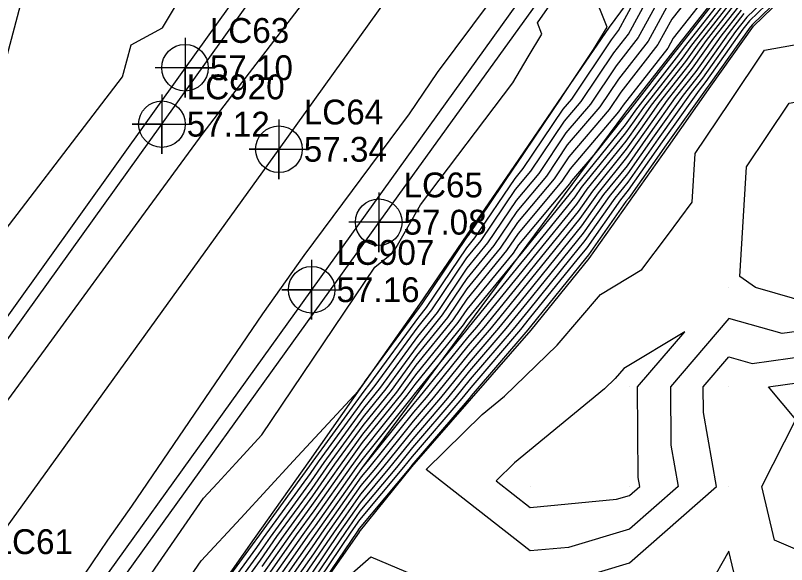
# Model space of a CAD drawing. Extents: x 2188792 to 2191981, y 386090 to 389710.
# Drawn here: x 2189698.4 to 2189776.1, y 387002.3 to 387057.5 of the extents above; entities that cross this region are included whole.
import ezdxf

# ---------------------------------------------------------------- set-up
doc = ezdxf.new("R2010")
doc.units = 0
for name, color, linetype in [('DTM Contours Major', 7, 'Continuous'), ('DTM Contours Minor', 7, 'Continuous'), ('Exist DTM QL2 LIDAR Elevation Point', 7, 'Continuous'), ('Exist Roads EOP', 7, 'Continuous'), ('Exist Roads EOP Cogo Elevation', 7, 'Continuous'), ('Exist Roads EOP Cogo Number', 7, 'Continuous'), ('Exist Roads EOP Cogo Point CELL', 7, 'Continuous'), ('Exist Roads EOT', 7, 'Continuous'), ('Exist Roads EOT Cogo Elevation', 7, 'Continuous'), ('Exist Roads EOT Cogo Number', 7, 'Continuous'), ('Exist Roads EOT Cogo Point CELL', 7, 'Continuous'), ('PH Exist DTM Breakline', 7, 'Continuous')]:
    doc.layers.add(name, color=color, linetype=linetype)

msp = doc.modelspace()

# ---------------------------------------------------------------- linework, layer by layer
at = {"layer": 'DTM Contours Major'}
for points in [[(2189690.321, 386970.473), (2189702.993, 386988.788), (2189704.322, 386990.511), (2189705.738, 386992.346), (2189707.249, 386994.304), (2189717.366, 387008.941), (2189718.756, 387010.444), (2189720.618, 387012.458), (2189723.242, 387015.296), (2189734.595, 387032.184), (2189736.495, 387033.703), (2189737.964, 387036.279), (2189739.21, 387038.462), (2189748.491, 387050.734), (2189750.059, 387053.337), (2189751.431, 387055.614), (2189750.977, 387056.76), (2189764.817, 387076.56)], [(2189770.37, 387059.498), (2189766.477, 387054.529), (2189765.536, 387053.205), (2189761.639, 387048.232), (2189760.7, 387046.911), (2189759.834, 387045.683), (2189755.394, 387040.191), (2189754.733, 387039.253), (2189749.901, 387033.319), (2189749.274, 387032.543), (2189744.104, 387026.197), (2189743.867, 387025.921), (2189741.118, 387022.531), (2189738.569, 387019.387), (2189738.376, 387019.123), (2189733.284, 387012.793), (2189732.715, 387012.012), (2189728.599, 387006.151), (2189728.008, 387005.341), (2189723.907, 386999.502)], [(2189764.365, 387059.07), (2189762.119, 387054.93), (2189759.122, 387051.105), (2189757.255, 387048.316), (2189753.984, 387044.476), (2189751.876, 387041.338), (2189748.903, 387037.778), (2189746.599, 387034.358), (2189743.864, 387031.031), (2189741.397, 387027.375), (2189738.858, 387024.244), (2189735.713, 387019.939), (2189733.438, 387017.112), (2189730.023, 387012.424), (2189728.266, 387009.921), (2189724.72, 387005.059), (2189723.055, 387002.687), (2189719.368, 386997.637)], [(2189771.771, 387057.69), (2189770.182, 387055.661), (2189767.252, 387051.539), (2189765.651, 387049.496), (2189762.729, 387045.388), (2189760.033, 387041.567), (2189758.204, 387039.304), (2189755.59, 387035.598), (2189753.605, 387033.16), (2189749.906, 387028.583), (2189747.795, 387025.992), (2189744.151, 387021.741), (2189741.932, 387019.006), (2189738.424, 387014.917), (2189736.076, 387012.007), (2189733.129, 387008.475), (2189731.016, 387005.466), (2189728.189, 387001.282)], [(2189780.243, 387002.408), (2189774.836, 387004.714), (2189773.564, 387010.122), (2189776.981, 387016.86), (2189774.225, 387020.123), (2189780.243, 387020.978), (2189780.976, 387020.123), (2189781.842, 387018.524), (2189784.658, 387010.122), (2189780.243, 387002.408)]]:
    msp.add_lwpolyline(points, dxfattribs=at)
at = {"layer": 'DTM Contours Minor'}
for points in [[(2189809.4, 387152.406), (2189801.396, 387139.864), (2189794.846, 387131.758), (2189788.146, 387120.877), (2189781.876, 387111.472), (2189771.155, 387095.136), (2189767.896, 387090.241), (2189758.451, 387075.833), (2189755.214, 387070.994), (2189740.876, 387051.783), (2189738.057, 387047.608), (2189727.447, 387033.342), (2189723.289, 387027.488), (2189710.113, 387008.133), (2189707.688, 387004.715), (2189696.068, 386987.603)], [(2189696.471, 387049.421), (2189699.118, 387059.215), (2189708.661, 387064.393), (2189716.242, 387077.088), (2189716.33, 387084.342), (2189716.986, 387089.265), (2189724.478, 387097.632), (2189725.68, 387102.327), (2189726.316, 387104.883), (2189727.566, 387106.251), (2189729.192, 387108.705), (2189725.665, 387114.356), (2189721.969, 387117.878), (2189720.487, 387119.888), (2189714.937, 387125.854), (2189714.651, 387126.766), (2189711.679, 387129.357), (2189708.744, 387132.995), (2189708.343, 387133.816), (2189703.681, 387138.317), (2189702.831, 387140.801), (2189699.533, 387144.461), (2189697.848, 387149.71)], [(2189696.907, 387017.785), (2189701.439, 387023.972), (2189711.162, 387037.242), (2189717.34, 387045.675), (2189728.32, 387060.015), (2189733.86, 387067.386), (2189739.131, 387074.278), (2189747.437, 387085.333), (2189756.453, 387096.182), (2189763.575, 387105.718), (2189769.232, 387112.608), (2189780.82, 387128.185), (2189787.157, 387139.391), (2189793.588, 387149.149)], [(2189693.956, 387031.466), (2189709.218, 387051.316), (2189710.092, 387054.548), (2189713.24, 387056.257), (2189723.102, 387072.77)], [(2189820.247, 387004.866), (2189810.804, 387009.564), (2189810.246, 387008.7), (2189810.022, 387009.897), (2189809.682, 387010.122), (2189803.138, 387013.015), (2189800.245, 387015.476), (2189796.388, 387016.266), (2189790.244, 387015.277), (2189787.619, 387020.123), (2189780.243, 387028.73), (2189778.618, 387028.499), (2189772.927, 387030.124), (2189771.347, 387031.229), (2189772.012, 387042.269), (2189774.139, 387045.431), (2189776.314, 387048.667), (2189788.413, 387050.787), (2189788.816, 387051.179), (2189789.608, 387051.909), (2189788.726, 387065.168)], [(2189717.798, 386997.228), (2189722.714, 387003.962), (2189723.405, 387004.946), (2189728.132, 387011.429), (2189728.947, 387012.589), (2189733.5, 387018.839), (2189734.647, 387020.265), (2189738.974, 387026.187), (2189740.343, 387027.876), (2189743.872, 387033.102), (2189745.319, 387034.863), (2189748.781, 387040.003), (2189750.324, 387041.85), (2189753.707, 387046.886), (2189755.368, 387048.836), (2189758.653, 387053.743), (2189760.14, 387055.641), (2189764.093, 387062.926)], [(2189780.243, 387026.146), (2189775.606, 387025.487), (2189770.242, 387027.018), (2189764.362, 387020.123), (2189764.402, 387014.282), (2189765.149, 387010.122), (2189760.241, 387005.813), (2189754.098, 387003.978), (2189750.24, 387003.616), (2189739.784, 387011.833), (2189745.409, 387017.359), (2189747.649, 387019.202), (2189752.969, 387024.33), (2189757.324, 387029.426), (2189761.491, 387031.946), (2189764.057, 387035.381), (2189766.554, 387038.726), (2189766.849, 387043.614), (2189770.309, 387048.76), (2189773.849, 387054.026), (2189777.609, 387054.685), (2189780.392, 387057.388), (2189785.853, 387062.425)], [(2189717.013, 386997.024), (2189722.543, 387004.599), (2189722.747, 387004.89), (2189728.066, 387012.183), (2189728.409, 387012.672), (2189733.531, 387019.703), (2189734.114, 387020.428), (2189739.031, 387027.158), (2189739.816, 387028.126), (2189743.875, 387034.138), (2189744.679, 387035.116), (2189748.72, 387041.116), (2189749.548, 387042.106), (2189753.568, 387048.091), (2189754.424, 387049.096), (2189758.419, 387055.063), (2189759.151, 387055.997), (2189762.508, 387062.186)], [(2189764.229, 387060.998), (2189761.129, 387055.285), (2189758.888, 387052.424), (2189756.312, 387048.576), (2189753.845, 387045.681), (2189751.1, 387041.594), (2189748.842, 387038.891), (2189745.959, 387034.611), (2189743.868, 387032.066), (2189740.87, 387027.626), (2189738.916, 387025.216), (2189735.18, 387020.102), (2189733.469, 387017.976), (2189729.485, 387012.507), (2189728.199, 387010.675), (2189724.062, 387005.003), (2189722.884, 387003.325), (2189718.583, 386997.433)], [(2189767.949, 387061.541), (2189764.501, 387057.141), (2189763.108, 387054.574), (2189759.357, 387049.786), (2189758.199, 387048.057), (2189754.123, 387043.271), (2189752.653, 387041.082), (2189748.964, 387036.666), (2189747.239, 387034.105), (2189743.861, 387029.995), (2189741.923, 387027.125), (2189738.8, 387023.273), (2189736.245, 387019.776), (2189733.408, 387016.248), (2189730.562, 387012.342), (2189728.332, 387009.167), (2189725.378, 387005.115), (2189723.225, 387002.05)], [(2189769.026, 387060.814), (2189764.637, 387055.213), (2189764.098, 387054.218), (2189759.591, 387048.467), (2189759.143, 387047.797), (2189754.261, 387042.066), (2189753.429, 387040.826), (2189749.025, 387035.553), (2189747.878, 387033.852), (2189743.857, 387028.959), (2189742.45, 387026.875), (2189738.743, 387022.301), (2189736.778, 387019.613), (2189733.377, 387015.384), (2189731.1, 387012.259), (2189728.399, 387008.413), (2189726.035, 387005.172), (2189723.396, 387001.413)], [(2189769.81, 387060.221), (2189764.996, 387054.076), (2189764.849, 387053.871), (2189760.035, 387047.726), (2189759.889, 387047.521), (2189759.754, 387047.33), (2189756.848, 387043.734), (2189754.4, 387040.861), (2189754.205, 387040.57), (2189749.085, 387034.441), (2189748.518, 387033.599), (2189743.854, 387027.923), (2189742.977, 387026.625), (2189738.685, 387021.33), (2189737.311, 387019.45), (2189733.346, 387014.521), (2189731.638, 387012.177), (2189728.465, 387007.659), (2189726.693, 387005.228), (2189723.566, 387000.776)], [(2189776.307, 387060.195), (2189772.612, 387056.605), (2189772.404, 387056.34), (2189768.281, 387050.54), (2189768.058, 387050.255), (2189763.947, 387044.473), (2189760.153, 387039.097), (2189759.89, 387038.771), (2189756.104, 387033.405), (2189755.828, 387033.065), (2189750.285, 387026.207), (2189750.009, 387025.869), (2189744.321, 387019.234), (2189744.103, 387018.964), (2189738.343, 387012.251), (2189738.193, 387012.065), (2189733.037, 387005.884), (2189732.78, 387005.517), (2189727.833, 386998.195)], [(2189775.671, 387060.211), (2189772.332, 387056.967), (2189771.663, 387056.114), (2189767.938, 387050.873), (2189767.256, 387050.002), (2189763.541, 387044.778), (2189760.113, 387039.92), (2189759.328, 387038.949), (2189755.933, 387034.136), (2189755.087, 387033.097), (2189750.159, 387026.999), (2189749.271, 387025.91), (2189744.265, 387020.07), (2189743.379, 387018.978), (2189738.37, 387013.14), (2189737.487, 387012.046), (2189733.068, 387006.747), (2189732.192, 387005.5), (2189727.951, 386999.224)], [(2189775.034, 387060.226), (2189772.051, 387057.328), (2189770.922, 387055.887), (2189767.595, 387051.206), (2189766.453, 387049.749), (2189763.135, 387045.083), (2189760.073, 387040.743), (2189758.766, 387039.126), (2189755.761, 387034.867), (2189754.346, 387033.128), (2189750.032, 387027.791), (2189748.533, 387025.951), (2189744.208, 387020.906), (2189742.656, 387018.992), (2189738.397, 387014.028), (2189736.782, 387012.026), (2189733.099, 387007.611), (2189731.604, 387005.483), (2189728.07, 387000.253)], [(2189694.937, 386972.126), (2189701.702, 386981.904), (2189705.036, 386986.223), (2189708.586, 386990.823), (2189712.374, 386995.732), (2189717.133, 387002.617), (2189721.107, 387006.915), (2189726.432, 387012.673), (2189732.935, 387019.706), (2189733.562, 387020.567), (2189733.582, 387020.591), (2189739.089, 387028.13), (2189739.289, 387028.377), (2189743.879, 387035.174), (2189744.039, 387035.369), (2189748.66, 387042.228), (2189748.771, 387042.362), (2189753.429, 387049.296), (2189753.48, 387049.355), (2189756.636, 387054.069), (2189757.992, 387056.32), (2189756.554, 387059.949)], [(2189770.09, 387059.859), (2189765.736, 387054.303), (2189765.193, 387053.538), (2189760.837, 387047.979), (2189760.295, 387047.216), (2189759.794, 387046.507), (2189754.833, 387040.369), (2189754.561, 387039.985), (2189749.16, 387033.351), (2189749.148, 387033.335), (2189748.983, 387033.133), (2189743.85, 387026.887), (2189743.504, 387026.374), (2189738.627, 387020.359), (2189737.844, 387019.286), (2189733.315, 387013.657), (2189732.177, 387012.094), (2189728.532, 387006.905), (2189727.35, 387005.284), (2189723.737, 387000.139)], [(2189770.65, 387059.136), (2189767.218, 387054.755), (2189765.879, 387052.872), (2189762.442, 387048.485), (2189761.106, 387046.606), (2189759.874, 387044.86), (2189755.956, 387040.014), (2189754.904, 387038.522), (2189750.642, 387033.287), (2189749.4, 387031.751), (2189744.842, 387026.156), (2189743.924, 387025.085), (2189739.038, 387019.061), (2189738.532, 387018.472), (2189733.253, 387011.929), (2189728.665, 387005.397), (2189724.078, 386998.864)], [(2189770.931, 387058.774), (2189767.959, 387054.982), (2189766.222, 387052.538), (2189763.244, 387048.738), (2189761.512, 387046.302), (2189759.914, 387044.037), (2189756.518, 387039.836), (2189755.076, 387037.791), (2189751.383, 387033.255), (2189749.527, 387030.959), (2189745.58, 387026.115), (2189743.981, 387024.249), (2189739.761, 387019.047), (2189738.505, 387017.583), (2189733.959, 387011.949), (2189733.222, 387011.066), (2189729.253, 387005.414), (2189728.546, 387004.368), (2189724.606, 386998.758)], [(2189771.211, 387058.413), (2189768.7, 387055.208), (2189766.565, 387052.205), (2189764.046, 387048.991), (2189761.918, 387045.997), (2189759.954, 387043.213), (2189757.08, 387039.659), (2189755.247, 387037.06), (2189752.124, 387033.224), (2189749.653, 387030.167), (2189746.318, 387026.074), (2189744.038, 387023.413), (2189740.485, 387019.033), (2189738.478, 387016.694), (2189734.664, 387011.968), (2189733.191, 387010.202), (2189729.841, 387005.431), (2189728.427, 387003.339), (2189725.135, 386998.652)], [(2189771.491, 387058.051), (2189769.441, 387055.435), (2189766.909, 387051.872), (2189764.849, 387049.244), (2189762.324, 387045.692), (2189759.993, 387042.39), (2189757.642, 387039.481), (2189755.419, 387036.329), (2189752.864, 387033.192), (2189749.78, 387029.375), (2189747.057, 387026.033), (2189744.094, 387022.577), (2189741.208, 387019.019), (2189738.451, 387015.806), (2189735.37, 387011.988), (2189733.16, 387009.338), (2189730.429, 387005.449), (2189728.308, 387002.31), (2189725.664, 386998.545)], [(2189761.06, 387020.123), (2189765.803, 387025.685), (2189759.662, 387021.972), (2189758.796, 387020.959), (2189757.739, 387019.94), (2189748.668, 387012.477), (2189746.837, 387010.679), (2189750.24, 387008.004), (2189758.941, 387008.821), (2189760.241, 387009.21), (2189761.28, 387010.122), (2189761.122, 387011.003), (2189761.06, 387020.123)], [(2189770.901, 387000.78), (2189770.242, 387003.583), (2189768.255, 387000.121), (2189762.025, 386998.338), (2189760.241, 386998.646), (2189757.594, 386997.473), (2189752.556, 387000.121), (2189760.241, 387002.416), (2189769.018, 387010.122), (2189767.681, 387017.562), (2189767.664, 387020.123), (2189770.242, 387023.147), (2189772.595, 387022.475), (2189780.243, 387023.562)], [(2189728.28, 386997.816), (2189734.197, 387003.02), (2189747.529, 386997.409)]]:
    msp.add_lwpolyline(points, dxfattribs=at)
at = {"layer": 'Exist DTM QL2 LIDAR Elevation Point'}
for p, q in [((2189770.242, 387030.124), (2189770.242, 387030.124)), ((2189760.241, 387020.123), (2189760.241, 387020.123)), ((2189770.242, 387020.123), (2189770.242, 387020.123)), ((2189750.24, 387010.122), (2189750.24, 387010.122)), ((2189760.241, 387010.122), (2189760.241, 387010.122)), ((2189770.242, 387010.122), (2189770.242, 387010.122))]:
    msp.add_line(p, q, dxfattribs=at)
at = {"layer": 'Exist Roads EOP'}
for points in [[(2190313.986, 387884.141), (2190285.547, 387843.636), (2190254.588, 387800.045), (2190225.155, 387759.32), (2190194.829, 387717.425), (2190164.291, 387675.101), (2190137.229, 387637.301), (2190105.098, 387592.774), (2190071.411, 387546.221), (2190039.296, 387501.568), (2190007.542, 387457.958), (2189976.844, 387415.407), (2189936.359, 387359.145), (2189907.138, 387318.716), (2189868.636, 387265.243), (2189836.428, 387220.463), (2189805.695, 387177.815), (2189775.592, 387135.957), (2189745.498, 387094.055), (2189715.496, 387052.249), (2189683.869, 387008.07), (2189653.218, 386965.867), (2189623.729, 386924.667)], [(2190335.128, 387868.989), (2190306.373, 387829.271), (2190274.581, 387784.921), (2190245.133, 387744.071), (2190214.553, 387701.741), (2190184.89, 387660.475), (2190157.493, 387622.204), (2190126.048, 387578.501), (2190091.216, 387530.568), (2190059.634, 387486.726), (2190026.932, 387441.783), (2189997.689, 387401.032), (2189957.023, 387344.154), (2189927.908, 387303.922), (2189889.008, 387250.224), (2189856.606, 387205.5), (2189825.68, 387162.612), (2189795.668, 387120.822), (2189765.955, 387079.619), (2189734.998, 387036.704), (2189703.849, 386993.356), (2189673.984, 386951.979), (2189643.253, 386909.427)]]:
    msp.add_lwpolyline(points, dxfattribs=at)
at = {"layer": 'Exist Roads EOP Cogo Point CELL'}
for points in [[(2189715.496, 387055.249), (2189715.496, 387049.249), (2189715.496, 387052.249), (2189718.496, 387052.249), (2189712.496, 387052.249)], [(2189734.998, 387039.704), (2189734.998, 387033.704), (2189734.998, 387036.704), (2189737.998, 387036.704), (2189731.998, 387036.704)]]:
    msp.add_lwpolyline(points, dxfattribs=at)
for centre in [(2189715.496, 387052.249), (2189734.998, 387036.704)]:
    msp.add_circle(centre, 2.344, dxfattribs=at)
at = {"layer": 'Exist Roads EOT'}
for points in [[(2190174.375, 387667.889), (2190147.471, 387630.495), (2190115.247, 387585.778), (2190081.202, 387538.232), (2190049.502, 387494.256), (2190017.538, 387450.182), (2189987.334, 387408.357), (2189946.666, 387352.019), (2189917.402, 387311.129), (2189878.955, 387257.772), (2189846.565, 387212.819), (2189815.837, 387170.306), (2189785.374, 387128.351), (2189755.717, 387086.921), (2189724.953, 387044.041), (2189693.727, 387000.805), (2189663.933, 386959.217), (2189633.425, 386917.196)], [(2189989.253, 387391.986), (2189958.581, 387349.453), (2189928.09, 387307.216), (2189909.67, 387281.603), (2189884.44, 387246.513), (2189852.91, 387202.766), (2189821.507, 387159.305), (2189790.01, 387115.85), (2189759.16, 387072.957), (2189728.247, 387029.91), (2189696.407, 386985.689), (2189665.45, 386942.736), (2189635.049, 386900.502)], [(2189619.904, 386917.168), (2189650.19, 386959.038), (2189680.959, 387001.734), (2189713.171, 387046.57), (2189739.87, 387083.883), (2189771.556, 387127.847), (2189803.188, 387171.311), (2189835.065, 387215.496), (2189866.485, 387259.202), (2189892.308, 387295.019), (2189910.407, 387320.236), (2189942.075, 387364.22)]]:
    msp.add_lwpolyline(points, dxfattribs=at)
at = {"layer": 'Exist Roads EOT Cogo Point CELL'}
for points in [[(2189713.171, 387049.57), (2189713.171, 387043.57), (2189713.171, 387046.57), (2189710.171, 387046.57), (2189716.171, 387046.57)], [(2189724.953, 387047.041), (2189724.953, 387041.041), (2189724.953, 387044.041), (2189721.953, 387044.041), (2189727.953, 387044.041)], [(2189728.247, 387032.91), (2189728.247, 387026.91), (2189728.247, 387029.91), (2189725.247, 387029.91), (2189731.247, 387029.91)]]:
    msp.add_lwpolyline(points, dxfattribs=at)
for centre in [(2189713.171, 387046.57), (2189724.953, 387044.041), (2189728.247, 387029.91)]:
    msp.add_circle(centre, 2.344, dxfattribs=at)
at = {"layer": 'PH Exist DTM Breakline'}
for points in [[(2189791.244, 387081.417), (2189785.633, 387076.29), (2189780.022, 387071.163), (2189774.864, 387065.758), (2189769.707, 387060.354), (2189764.723, 387053.993), (2189759.74, 387047.633), (2189754.442, 387040.492), (2189749.145, 387033.351), (2189743.848, 387026.211), (2189738.55, 387019.07), (2189733.253, 387011.929), (2189728.665, 387005.397), (2189724.078, 386998.864), (2189719.49, 386992.332), (2189714.902, 386985.799)], [(2189780.243, 387080.129), (2189775.664, 387077.506), (2189769.813, 387072.074), (2189764.002, 387064.208), (2189758.191, 387056.342), (2189753.421, 387049.372), (2189748.65, 387042.402), (2189743.88, 387035.432), (2189739.109, 387028.462), (2189733.563, 387020.597), (2189728.017, 387012.732), (2189722.471, 387004.866), (2189716.926, 386997.001), (2189711.359, 386989.34), (2189705.791, 386981.679), (2189700.224, 386974.018), (2189694.657, 386966.357)], [(2189733.024, 387005.524), (2189738.338, 387012.069), (2189744.34, 387018.96), (2189750.342, 387025.85), (2189756.188, 387033.049), (2189760.173, 387038.682), (2189764.158, 387044.315), (2189768.448, 387050.378), (2189772.738, 387056.442), (2189776.594, 387060.188), (2189784.161, 387067.166), (2189792.199, 387072.893), (2189800.237, 387078.62)], [(2189733.024, 387005.524), (2189727.823, 386998.111), (2189722.622, 386990.697), (2189717.421, 386983.283), (2189712.048, 386975.754), (2189706.675, 386968.224), (2189701.302, 386960.695), (2189696.271, 386953.485), (2189691.241, 386946.275), (2189686.211, 386939.065), (2189681.181, 386931.855), (2189676.534, 386925.321), (2189671.888, 386918.787), (2189667.242, 386912.253), (2189662.596, 386905.719), (2189657.949, 386899.185), (2189653.071, 386892.669), (2189648.193, 386886.152), (2189643.315, 386879.636), (2189638.437, 386873.12), (2189633.559, 386866.603)]]:
    msp.add_lwpolyline(points, dxfattribs=at)

# ---------------------------------------------------------------- texts
at = {"layer": 'Exist Roads EOP Cogo Elevation'}
for s, p in [('57.10', (2189717.996, 387050.999)), ('57.08', (2189737.498, 387035.454))]:
    msp.add_text(s, height=2.5, dxfattribs=at).set_placement(p)
at = {"layer": 'Exist Roads EOP Cogo Number'}
for s, p in [('LC63', (2189717.996, 387054.749)), ('LC65', (2189737.498, 387039.204))]:
    msp.add_text(s, height=2.5, dxfattribs=at).set_placement(p)
at = {"layer": 'Exist Roads EOT Cogo Elevation'}
for s, p in [('57.12', (2189715.671, 387045.32)), ('57.34', (2189727.453, 387042.791)), ('57.16', (2189730.747, 387028.66))]:
    msp.add_text(s, height=2.5, dxfattribs=at).set_placement(p)
at = {"layer": 'Exist Roads EOT Cogo Number'}
for s, p in [('LC920', (2189715.671, 387049.07)), ('LC64', (2189727.453, 387046.541)), ('LC907', (2189730.747, 387032.41)), ('LC61', (2189696.227, 387003.305))]:
    msp.add_text(s, height=2.5, dxfattribs=at).set_placement(p)

doc.saveas('drawing.dxf')
